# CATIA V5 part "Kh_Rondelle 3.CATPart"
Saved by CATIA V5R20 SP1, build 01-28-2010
Part number: Rondelle 3
Bounding box of the stored display mesh (mm): x 0 to 2.5, y -13.5 to 13.5, z -13.49 to 13.49
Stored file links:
  G:\Khaled_CFAO_2011\SIL\SIL_GR1\tmerino\Khaled\CAD_Thinkmotion\Kh_Rondelle 3.CATPart
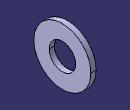
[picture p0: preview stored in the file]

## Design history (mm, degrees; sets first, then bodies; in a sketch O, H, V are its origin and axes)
Body1 (main body)
  Sketch1 on yz-plane, origin (0, 0, 0), H (0, 1, 0), V (0, 0, 1)
    circle A1 centre (0, 0) radius 6.25
    circle A2 centre (0, 0) radius 13.5
    radius A2 = 13.5
    radius A1 = 6.25
  Pad1: profile Sketch1, direction (1, 0, 0), length 2.5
